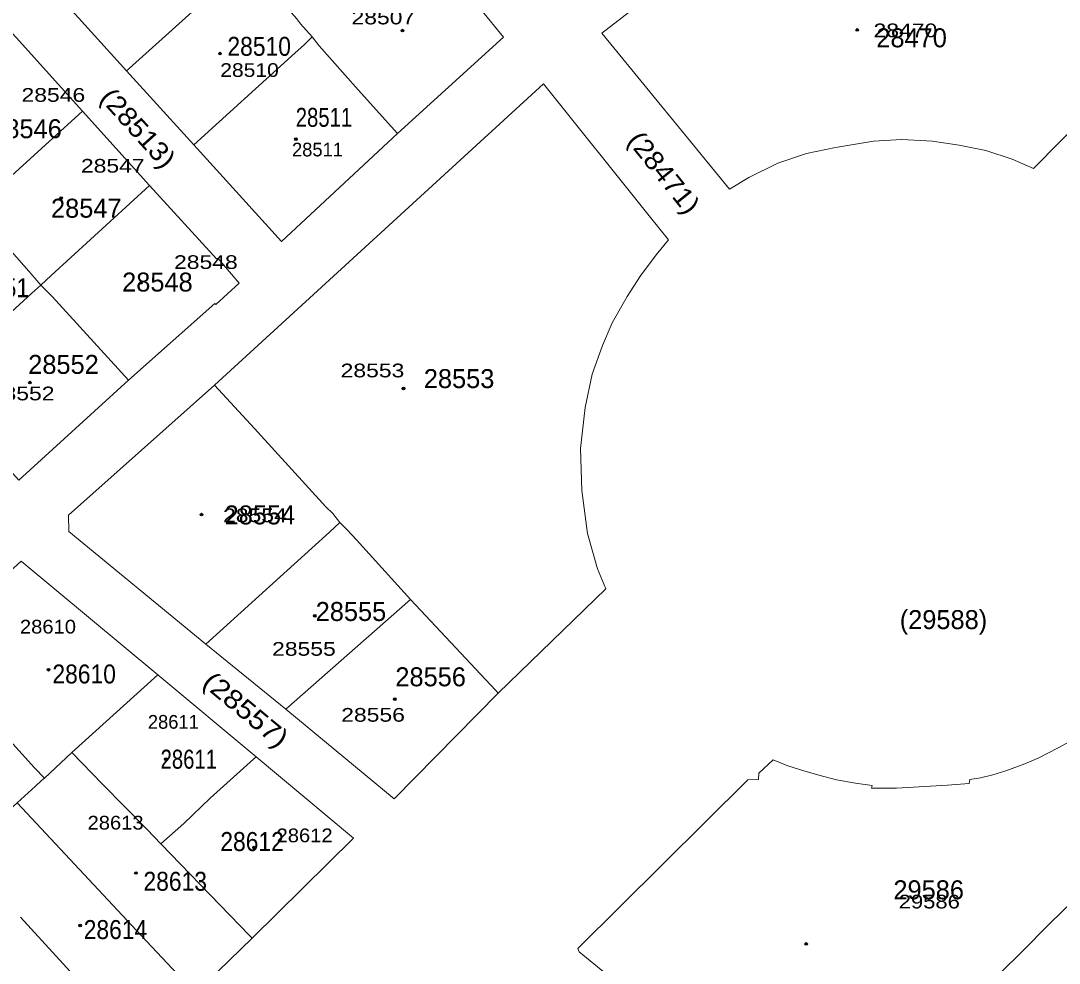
# Model space of a CAD drawing. Extents: x 650553 to 652508, y 239277 to 241647.
# Drawn here: x 651532.3 to 651729.3, y 240545.4 to 240724.2 of the extents above; entities that cross this region are included whole.
import ezdxf

# ---------------------------------------------------------------- set-up
doc = ezdxf.new("R2010")
doc.units = 0
doc.header["$PDMODE"] = 32
doc.header["$PDSIZE"] = 0.5
for name, color, linetype in [('19', 7, 'Continuous'), ('20', 7, 'Continuous'), ('6', 7, 'Continuous')]:
    doc.layers.add(name, color=color, linetype=linetype)
doc.layers.add('3', color=7, linetype='Continuous', lineweight=13)
doc.layers.add('5', color=7, linetype='Continuous', lineweight=13)

msp = doc.modelspace()

# ---------------------------------------------------------------- linework, layer by layer
at = {"layer": '3'}
for p, q in [((651544.042, 240707.095), (651556.77, 240692.988)), ((651582.634, 240593.616), (651567.438, 240605.943)), ((651698.449, 240578.644), (651708.175, 240579.209))]:
    msp.add_line(p, q, dxfattribs=at)
for points in [[(651666.816, 240692.253), (651642.596, 240721.898), (651682.54, 240752.71), (651700.34, 240766.81), (651718.3, 240780.69), (651736.3, 240794.4)], [(651603.824, 240702.804), (651623.93, 240721.142), (651606.935, 240741.896)], [(651492.971, 240720.815), (651513.155, 240740.984), (651531.466, 240721.038), (651544.042, 240707.095)], [(651539.59, 240728.862), (651552.382, 240714.704), (651565.174, 240700.661)], [(651666.816, 240692.253), (651670.475, 240694.498), (651675.984, 240697.224), (651681.411, 240699.022), (651686.904, 240700.185), (651694.099, 240701.383), (651699.482, 240701.668), (651705.326, 240701.397), (651710.373, 240700.626), (651715.395, 240699.613), (651720.434, 240697.99), (651724.445, 240696.209), (651744.578, 240716.581)], [(651569.097, 240655.103), (651631.473, 240712.24), (651651.578, 240687.184)], [(651565.174, 240700.661), (651581.774, 240682.357), (651603.824, 240702.804)], [(651556.77, 240692.988), (651569.472, 240679.033), (651569.738, 240679.174), (651573.765, 240674.42), (651569.342, 240670.379), (651569.125, 240670.581), (651552.783, 240656.051)], [(651651.578, 240687.184), (651655.248, 240682.631), (651652.85, 240679.834), (651649.926, 240675.852), (651647.344, 240671.936), (651644.514, 240666.913), (651642.696, 240662.62), (651640.732, 240657.145), (651639.383, 240650.847), (651638.524, 240643.078), (651638.797, 240635.087), (651639.871, 240626.96), (651641.724, 240620.249), (651643.307, 240616.472), (651622.905, 240596.67), (651603.175, 240576.613), (651582.634, 240593.616)], [(651552.783, 240656.051), (651531.957, 240637.06), (651515.523, 240655.238)], [(651567.438, 240605.943), (651541.448, 240627.305), (651541.405, 240630.393), (651569.097, 240655.103)], [(651514.288, 240605.241), (651532.372, 240621.712), (651558.3, 240600.133)], [(651558.3, 240600.133), (651576.968, 240584.586), (651595.445, 240569.14), (651576.219, 240550.158), (651565.481, 240539.702), (651554.984, 240529.272), (651535.929, 240510.959), (651512.56, 240536.549), (651501.394, 240548.39)], [(651732.727, 240588.221), (651729.118, 240586.307), (651725.471, 240584.379), (651722.848, 240583.22), (651719.197, 240581.891), (651716.775, 240581.139), (651714.429, 240580.567), (651712.373, 240580.275), (651712.25, 240579.538), (651708.175, 240579.209)], [(651675.049, 240583.986), (651672.371, 240581.467), (651672.263, 240580.246), (651670.257, 240580.209), (651638.02, 240548.196), (651638.241, 240547.558), (651684.3, 240509.906)], [(651698.449, 240578.644), (651693.762, 240578.604), (651693.874, 240579.113), (651690.683, 240579.59), (651687.111, 240580.192), (651683.715, 240581.075), (651680.878, 240581.884), (651677.888, 240582.884), (651675.049, 240583.986)]]:
    msp.add_lwpolyline(points, dxfattribs=at)
at = {"layer": '5'}
for p, q in [((651565.174, 240700.661), (651583.675, 240717.478)), ((651582.634, 240593.616), (651606.282, 240614.402)), ((651558.3, 240600.133), (651542.01, 240585.362))]:
    msp.add_line(p, q, dxfattribs=at)
for points in [[(651552.382, 240714.704), (651552.882, 240715.156), (651572.363, 240732.75), (651573.247, 240733.606), (651575.193, 240735.321), (651573.717, 240737.3)], [(651587.592, 240721.16), (651585.419, 240723.664), (651584.715, 240724.6), (651576.791, 240733.5)], [(651603.824, 240702.804), (651596.335, 240711.134), (651588.935, 240719.491), (651587.592, 240721.16), (651586.126, 240719.741), (651583.675, 240717.478)], [(651503.098, 240669.537), (651503.598, 240670.001), (651523.455, 240688.424), (651544.042, 240707.095)], [(651510.816, 240702.43), (651514.382, 240698.422), (651519.659, 240692.646), (651523.455, 240688.424), (651533.859, 240676.692), (651536.108, 240674.074), (651534.428, 240672.54), (651515.523, 240655.238)], [(651536.108, 240674.074), (651538.067, 240675.878), (651556.77, 240692.988)], [(651536.108, 240674.074), (651538.267, 240671.939), (651552.783, 240656.051)], [(651569.097, 240655.103), (651576.661, 240646.837), (651590.219, 240632.022), (651591.547, 240630.721), (651592.878, 240629.052), (651594.232, 240627.662), (651596.008, 240625.728), (651606.282, 240614.402)], [(651567.438, 240605.943), (651590.869, 240627.172), (651592.878, 240629.052)], [(651606.282, 240614.402), (651622.436, 240597.17), (651622.905, 240596.67)], [(651514.288, 240605.241), (651534.939, 240582.5), (651536.83, 240580.491)], [(651558.897, 240568.089), (651556.316, 240570.781), (651547.771, 240579.423), (651542.01, 240585.362), (651536.83, 240580.491), (651536.235, 240580.068), (651535.098, 240579.019), (651531.648, 240575.861)], [(651576.968, 240584.586), (651576.468, 240584.134), (651568.273, 240576.734), (651563.283, 240571.94), (651558.897, 240568.089)], [(651565.481, 240539.702), (651565.011, 240540.202), (651555.234, 240550.609), (651531.648, 240575.861), (651525.86, 240570.63), (651521.12, 240566.46), (651519.553, 240565.053), (651501.394, 240548.39)], [(651558.897, 240568.089), (651575.736, 240550.658), (651576.219, 240550.158)], [(651684.3, 240509.906), (651691.776, 240517.523), (651698.788, 240524.311), (651699.785, 240525.447), (651704.534, 240530.177), (651722.068, 240547.369), (651727.626, 240552.993), (651733.93, 240559.128), (651737.908, 240563.103)], [(651532.289, 240554.148), (651554.528, 240529.772), (651554.984, 240529.272)]]:
    msp.add_lwpolyline(points, dxfattribs=at)
at = {"layer": '6'}
for p in [(651604.75, 240722.35), (651691.035, 240722.481), (651570.126, 240717.991), (651584.538, 240701.758), (651539.989, 240690.584), (651555.136, 240674.519), (651534.067, 240655.567), (651604.923, 240654.455), (651566.628, 240630.523), (651588.09, 240611.334), (651537.592, 240601.101), (651603.273, 240595.507), (651559.833, 240584.111), (651576.622, 240567.372), (651554.181, 240562.532), (651543.569, 240552.566), (651681.318, 240549.063)]:
    msp.add_point(p, dxfattribs=at)

# ---------------------------------------------------------------- texts
at = {"layer": '19'}
for s, p in [('28470', (651694.645, 240719.189)), ('28546', (651526.719, 240701.947)), ('28547', (651538.058, 240686.86)), ('28548', (651551.556, 240672.851)), ('28552', (651533.738, 240657.225)), ('28553', (651608.793, 240654.53)), ('28554', (651570.995, 240628.667)), ('28555', (651588.275, 240610.347)), ('(29588)', (651699.091, 240608.806)), ('28556', (651603.395, 240597.954)), ('29586', (651697.886, 240557.541))]:
    msp.add_text(s, height=3.6, dxfattribs=at).set_placement(p)
for s, width, p in [('28510', 0.9, (651571.533, 240717.572)), ('28511', 0.8, (651584.494, 240704.101)), ('28551', 0.9, (651521.859, 240671.773)), ('28610', 0.9, (651538.326, 240598.49)), ('28611', 0.8, (651558.845, 240582.325)), ('28612', 0.9, (651570.185, 240566.699)), ('28613', 0.9, (651555.606, 240559.156)), ('28614', 0.9, (651544.265, 240549.996))]:
    msp.add_text(s, height=3.6, dxfattribs=dict(at, width=width)).set_placement(p)
for s, rotation, width, p in [('(28513)', 312.049, 1.1, (651547.126, 240709.431)), ('(28471)', 308.744, 1.1, (651647.236, 240701.418)), ('(28557)', 320.212, 1.15, (651566.544, 240598.255))]:
    msp.add_text(s, height=3.6, rotation=rotation, dxfattribs=dict(at, width=width)).set_placement(p)
at = {"layer": '20'}
for s, width, p in [('28507', 1.25, (651595.073, 240723.541)), ('28470', 1.25, (651694.118, 240721.1)), ('28510', 1.15, (651570.169, 240713.571)), ('28546', 1.25, (651532.463, 240708.849)), ('28547', 1.25, (651543.736, 240695.406)), ('28548', 1.25, (651561.402, 240677.132)), ('28553', 1.25, (651593.009, 240656.571)), ('28552', 1.25, (651526.637, 240652.209)), ('28554', 1.25, (651570.7, 240629.087)), ('28610', 1.1, (651532.167, 240607.964)), ('28555', 1.25, (651580.001, 240603.749)), ('28556', 1.25, (651593.118, 240591.234)), ('28613', 1.1, (651544.998, 240570.776)), ('28612', 1.1, (651580.856, 240568.368)), ('29586', 1.2, (651698.895, 240555.806))]:
    msp.add_text(s, height=2.6, dxfattribs=dict(at, width=width)).set_placement(p)
for s, p in [('28511', (651583.783, 240698.488)), ('28611', (651556.434, 240589.905))]:
    msp.add_text(s, height=2.6, dxfattribs=at).set_placement(p)

doc.saveas('drawing.dxf')
